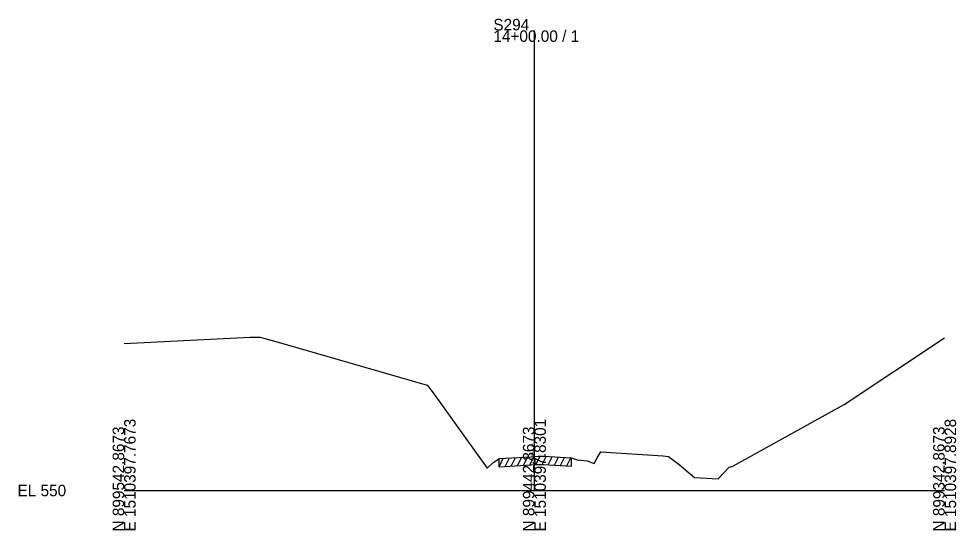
# Model space of a CAD drawing. Extents: x 974 to 2203, y -10 to 19041.
# Drawn here: x 974.3 to 1202.8, y 7990.3 to 8115 of the extents above; entities that cross this region are included whole.
import ezdxf

# ---------------------------------------------------------------- set-up
doc = ezdxf.new("R2010")
doc.units = 0
for name, color, linetype in [('RD_GPK_XS_Cell', 7, 'Continuous'), ('RD_XS_ExGround', 7, 'Continuous'), ('RD_XS_ExPaveRet', 7, 'Continuous'), ('RD_XS_TX_Elev_EX', 7, 'Continuous')]:
    doc.layers.add(name, color=color, linetype=linetype)

msp = doc.modelspace()

# ---------------------------------------------------------------- linework, layer by layer
at = {"layer": 'RD_GPK_XS_Cell'}
for p, q in [((1100, 8000), (1100, 8112.2)), ((1000, 8000), (1100, 8000)), ((1100, 8000), (1200, 8000))]:
    msp.add_line(p, q, dxfattribs=at)
at = {"layer": 'RD_XS_ExGround'}
msp.add_lwpolyline([(1000, 8035.85), (1030.72, 8037.4), (1033.17, 8037.4), (1038.7, 8035.88), (1073.83, 8025.65), (1075.05, 8024.13), (1088.46, 8005.47), (1089.91, 8006.72), (1090.39, 8007.11), (1091.38, 8007.8), (1099.23, 8008.25), (1100, 8008.31), (1100.95, 8008.38), (1102.31, 8008.35), (1108.98, 8007.96), (1110.45, 8007.46), (1111.3, 8007.36), (1112.88, 8007.25), (1114.59, 8006.57), (1115.29, 8007.98), (1116.16, 8009.44), (1131.38, 8008.48), (1132.73, 8008.31), (1135.26, 8006.33), (1139.03, 8003.2), (1144.77, 8002.82), (1147.46, 8005.69), (1148.41, 8005.91), (1171.71, 8018.9), (1175.52, 8021.01), (1200, 8037.25)], dxfattribs=at)
at = {"layer": 'RD_XS_ExPaveRet'}
for p, q in [((1091.38, 8005.8), (1092.41, 8007.86)), ((1091.38, 8005.8), (1091.38, 8007.8)), ((1092.88, 8005.88), (1093.91, 8007.94)), ((1094.38, 8005.97), (1095.41, 8008.03)), ((1095.88, 8006.06), (1096.91, 8008.12)), ((1097.38, 8006.14), (1098.41, 8008.2)), ((1098.88, 8006.23), (1099.91, 8008.3)), ((1100.38, 8006.34), (1101.39, 8008.37)), ((1101.88, 8006.36), (1102.86, 8008.32)), ((1103.38, 8006.29), (1104.35, 8008.23)), ((1104.88, 8006.2), (1105.85, 8008.14)), ((1106.38, 8006.11), (1107.35, 8008.05)), ((1107.88, 8006.02), (1108.85, 8007.97)), ((1108.98, 8007.96), (1108.98, 8005.96)), ((1091.38, 8005.8), (1099.23, 8006.25)), ((1099.23, 8006.25), (1100, 8006.31)), ((1100, 8006.31), (1100.95, 8006.38)), ((1100.95, 8006.38), (1102.31, 8006.35)), ((1102.31, 8006.35), (1108.98, 8005.96))]:
    msp.add_line(p, q, dxfattribs=at)

# ---------------------------------------------------------------- texts
at = {"layer": 'RD_GPK_XS_Cell'}
for s, p in [('S294', (1090, 8112.2)), ('14+00.00 / 1', (1090, 8109.4)), ('EL 550', (974, 7998.6))]:
    msp.add_text(s, height=2.8, dxfattribs=at).set_placement(p)
for s, p in [('E 1510397.7673', (1002.8, 7990)), ('E 1510397.8301', (1102.8, 7990)), ('E 1510397.8928', (1202.8, 7990)), ('N 899542.8673', (1000, 7990)), ('N 899442.8673', (1100, 7990)), ('N 899342.8673', (1200, 7990))]:
    msp.add_text(s, height=2.8, rotation=90, dxfattribs=at).set_placement(p)
at = {"layer": 'RD_XS_TX_Elev_EX'}
msp.add_text('554.15', height=0.75, rotation=90, dxfattribs=at).set_placement((1100, 8008.31))

doc.saveas('drawing.dxf')
